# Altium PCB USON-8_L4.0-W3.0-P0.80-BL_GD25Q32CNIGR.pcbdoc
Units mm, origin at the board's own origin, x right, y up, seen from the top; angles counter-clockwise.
Board outline 17.1 x 16.4 mm, 2 copper layers (Top Layer, Bottom Layer), stack 0.07 mm thick; 1 components, 0 nets, 10 pads, 0 vias.
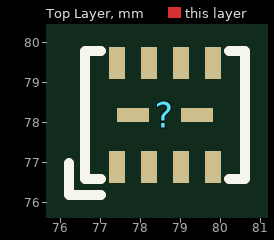
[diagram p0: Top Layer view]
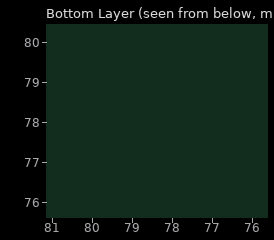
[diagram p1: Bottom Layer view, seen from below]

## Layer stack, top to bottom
Top Solder Mask Layer: solder mask 0.01, Dk 3.3
Top Layer: signal copper 0.035
Bottom Layer: signal copper 0.035
Bottom Solder Mask Layer: solder mask 0.01, Dk 3.3

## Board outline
86.95,69.85 69.85,69.85 69.85,86.25 86.95,86.25

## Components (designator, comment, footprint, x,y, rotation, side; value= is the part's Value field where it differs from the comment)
? "USON-8_L4.0-W3.0-P0.80-BL_GD25Q32CNIGR" USON-8_L4.0-W3.0-P0.80-BL_GD25Q32CNIGR 78.6,78.2 r0 top

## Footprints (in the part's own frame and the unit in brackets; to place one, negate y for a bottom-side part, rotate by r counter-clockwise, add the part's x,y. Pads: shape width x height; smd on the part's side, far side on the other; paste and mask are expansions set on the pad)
USON-8_L4.0-W3.0-P0.80-BL_GD25Q32CNIGR [mm]
  rect 0.4x0.8 smd paste+0 mask+0.051: 1(-1.2,-1.3) 2(-0.4,-1.3) 3(0.4,-1.3) 4(1.2,-1.3) 5(1.2,1.3) 6(0.4,1.3) 7(-0.4,1.3) 8(-1.2,1.3)
  rect 0.8x0.35 smd paste+0 mask+0.051: 9(-0.802,0) 10(0.798,0)
  silkscreen extent -2.4,-2 2,1.6

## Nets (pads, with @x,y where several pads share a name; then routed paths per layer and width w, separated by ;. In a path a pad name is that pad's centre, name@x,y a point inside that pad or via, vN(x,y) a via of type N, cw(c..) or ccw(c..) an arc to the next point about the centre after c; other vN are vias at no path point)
pads on no net: ?.1 ?.2 ?.3 ?.4 ?.5 ?.6 ?.7 ?.8 ?.9 ?.10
